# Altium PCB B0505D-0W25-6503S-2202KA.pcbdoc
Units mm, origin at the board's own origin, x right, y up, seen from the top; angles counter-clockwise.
Board outline 28 x 11 mm, 2 copper layers (Top Layer, Bottom Layer), stack 0.78 mm thick; 11 components, 8 nets, 30 pads, 14 vias.
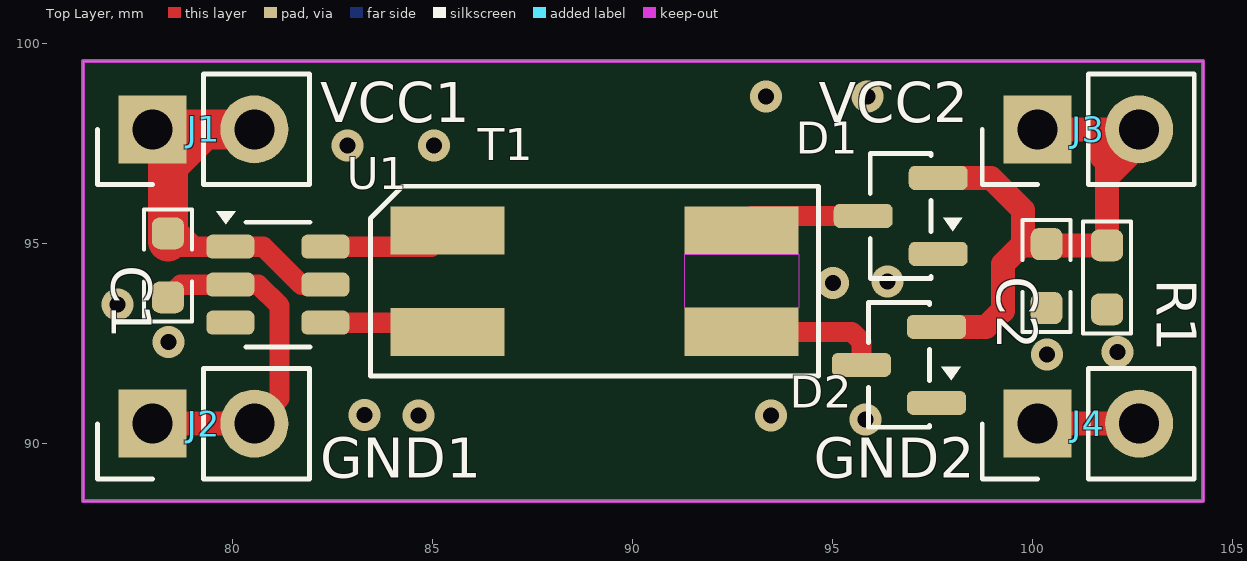
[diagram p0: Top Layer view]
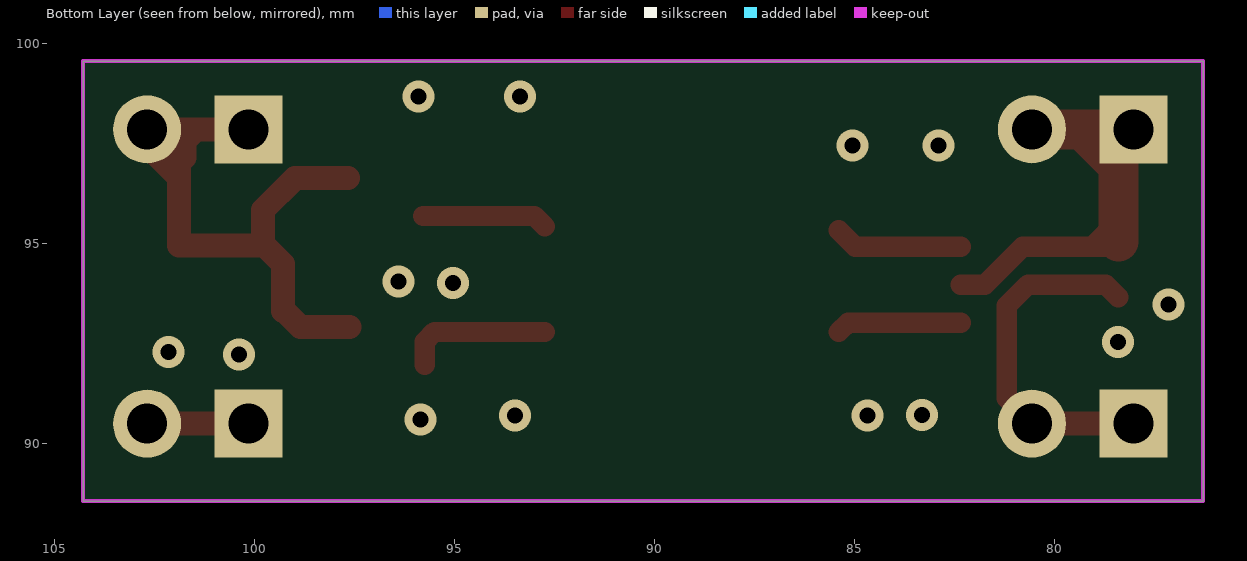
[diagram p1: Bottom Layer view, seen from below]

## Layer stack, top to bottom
Top Solder Mask Layer: solder mask 0.01, Dk 0
Top Layer: signal copper 0.035
dielectric 1: surface 0.71, FR4, Dk 4.5
Bottom Layer: signal copper 0.035
Bottom Solder Mask Layer: solder mask 0.01, Dk 0

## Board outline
76.273,99.565 104.273,99.565 104.273,88.565 76.273,88.565

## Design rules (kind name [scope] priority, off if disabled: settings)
BoardOutlineClearance copperThickness1oz [All] p0: genericclearance=0.254 ignorepadtopadclearanceinfootprint=FALSE except(0: Arc-SplitContinuation Track-SplitContinuation SMDPad-SplitContinuation THPad-SplitContinuation Via-SplitContinuation Fill-SplitContinuation Poly-SplitContinuation Region-SplitContinuation Text-SplitContinuation)
BoardOutlineClearance otherClearance [All] p0: genericclearance=0.254 ignorepadtopadclearanceinfootprint=FALSE except(0: Arc-SplitContinuation Track-SplitContinuation SMDPad-SplitContinuation THPad-SplitContinuation Via-SplitContinuation Fill-SplitContinuation Poly-SplitContinuation Region-SplitContinuation Text-SplitContinuation)
Clearance copperThickness1oz [All] p1: gap=0.178 ignorepadtopadclearanceinfootprint=FALSE
Clearance otherClearance [All] p1: gap=0.178 ignorepadtopadclearanceinfootprint=FALSE
DiffPairsRouting differentialPair [All] p1: maxuncoupledlength=10 minlimit=5 maxlimit=Infinity mostfreqgap=6 toplayer_minwidth=5 toplayer_prefwidth=100 toplayer_maxwidth=100 bottomlayer_minwidth=5 bottomlayer_prefwidth=100 bottomlayer_maxwidth=100
PasteMaskExpansion pasteMaskExpansion [All] p1: expansion=0
PlaneConnect innerPlane [All] p1: planeconnectstyle=Relief reliefexpansion=0.508 reliefentries=4 reliefconductorwidth=0.254 reliefairgap=0.254
PolygonConnect copper0 [All] p1: connectstyle=Direct reliefentries=4 reliefconductorwidth=10 polygonreliefangle="90 Angle" airgapwidth=10
RoutingVias viaSize [All] p1: viastyle="Through Hole" holewidth=24 minholewidth=11.811 maxholewidth=393.7 width=24 minwidth=11.811 maxwidth=393.7
SolderMaskExpansion solderMaskExpansion [All] p1: useseparateexpansions=TRUE expansion=2 expansionbottom=2
Width copperThickness1oz [All] p1: maxlimit=100 minlimit=5 preferedwidth=10

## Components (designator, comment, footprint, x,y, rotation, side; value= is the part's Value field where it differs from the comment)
C1 "1uF" C0603 78.393,94.461 r90 top
C2 "4.7uF" C0603 100.363,94.191 r90 top
D1 "BAT54S,215" SOT-23-3_L3.0-W1.7-P0.95-LS2.9-BR 96.713,95.694 r180 top
D2 "BAT54S,215" SOT-23-3_L3.0-W1.7-P0.95-LS2.9-BR 96.671,91.971 r180 top
J1 "KH-2.54PH180-1X2P-L11.5" HDR-TH_2P-P2.54-V-M 78.013,97.861 r90 top
J2 "KH-2.54PH180-1X2P-L11.5" HDR-TH_2P-P2.54-V-M 78.013,90.501 r90 top
J3 "KH-2.54PH180-1X2P-L11.5" HDR-TH_2P-P2.54-V-M 100.133,97.861 r90 top
J4 "KH-2.54PH180-1X2P-L11.5" HDR-TH_2P-P2.54-V-M 100.133,90.501 r90 top
R1 "4.7kΩ" R0603 101.873,94.161 r270 top
T1 "CMT2202KA" XFMR-SMD_CMT220KA 89.058,94.065 r0 top
U1 "CMP6503S" SOT-23-5_L2.9-W1.6-P0.95-LS2.8-BR 81.143,93.978 r0 top

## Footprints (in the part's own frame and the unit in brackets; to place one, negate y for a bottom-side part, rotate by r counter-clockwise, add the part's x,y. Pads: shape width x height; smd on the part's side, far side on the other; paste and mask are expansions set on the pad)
C0603 [mm]
  rrect50% 0.8x0.8 smd: 1(-0.8,0) 2(0.8,0)
  silkscreen extent -1.4,-0.6 1.4,0.6
HDR-TH_2P-P2.54-V-M [mm]
  rect 1.7x1.7 hole 1: 1(0,0)
  round 1.7 hole 1: 2(0,-2.54)
  silkscreen extent -1.38,-3.92 1.38,1.38
R0603 [mm]
  rrect50% 0.8x0.8 smd: 1(-0.8,0) 2(0.8,0)
  silkscreen extent -1.4,-0.6 1.4,0.6
SOT-23-3_L3.0-W1.7-P0.95-LS2.9-BR [mm]
  rrect50% 1.475x0.6 smd: 1(-0.937,0.95) 2(-0.937,-0.95) 3(0.938,0)
  silkscreen extent -1.54,-1.56 0.76,1.56
SOT-23-5_L2.9-W1.6-P0.95-LS2.8-BR [mm]
  rrect50% 1.2x0.6 smd: 1(-1.188,0.95) 2(-1.188,0) 3(-1.188,-0.95) 4(1.188,-0.95) 5(1.188,0) 6(1.188,0.95)
  silkscreen extent -1.54,-1.56 0.8,1.84
XFMR-SMD_CMT220KA [mm]
  rect 2.85x1.2 smd: 1(-3.675,1.27) 2(-3.675,-1.27) 3(3.675,-1.27) 4(3.675,1.27)
  silkscreen extent -5.6,-2.37 5.6,2.37

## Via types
v1: diameter 0.8, hole 0.4, Top Layer to Bottom Layer, 14 vias

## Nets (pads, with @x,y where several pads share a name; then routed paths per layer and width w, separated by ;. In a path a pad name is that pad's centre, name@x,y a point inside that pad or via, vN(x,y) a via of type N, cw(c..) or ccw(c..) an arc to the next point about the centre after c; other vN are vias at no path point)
$1N5: T1.2 U1.4 | length 3.1
  Top Layer w0.508: U1.4 85.151,93.027 T1.2
$1N6: T1.1 U1.6 | length 3.2
  Top Layer w0.508: U1.6 84.975,94.928 T1.1
$1N7: D1.3 T1.4 | length 3.2
  Top Layer w0.508: T1.4@92.733,95.431 92.996,95.694 D1.3
$1N8: D2.3 T1.3 | length 3.7
  Top Layer w0.508: T1.3 95.489,92.795 95.733,92.551 D2.3
GND1: C1.1 J2.1 J2.2 U1.2 | length 8.9
  Top Layer w0.508: C1.1 78.709,93.978 U1.2 80.651,93.978 81.183,93.446 81.183,91.131 J2.2
  Top Layer w0.6: J2.1 J2.2
  other v1: 84.663,90.701 83.303,90.721 78.403,92.541 77.133,93.481 82.884,97.451 85.043,97.451
GND2: C2.1 D1.1 D2.1 J4.1 J4.2 R1.2 | length 2.5
  Top Layer w0.6: J4.1 J4.2
  other v1: 95.833,90.601 93.472,90.701 100.373,92.231 102.133,92.291 95.023,94.021 96.383,94.061 93.345,98.676 95.885,98.676
VCC1: C1.2 J1.1 J1.2 U1.1 U1.5 | length 12.2
  Top Layer w0.508: J1.1 J1.1@78.393,97.481 ; C1.2@78.393,95.051 C1.2@78.421,95.024 ; C1.2 78.726,94.928 79.046,94.928 ; C1.2@78.393,95.581 79.046,94.928 ; U1.5 81.731,93.978 80.781,94.928 U1.1 79.046,94.928
  Top Layer w1: J1.1 79.303,97.861 ; C1.2@78.393,95.051 C1.2 78.393,95.581 78.393,96.951 ; J1.1@78.393,97.481 78.393,96.951 ; J1.2 79.303,97.861 ; 78.393,96.951 79.303,97.861
VCC2: C2.2 D1.2 D2.2 J3.1 J3.2 R1.1 | length 17.2
  Top Layer w0.6: D2.2 98.843,92.921 99.243,93.321 99.273,93.321 99.273,94.491 99.773,94.991 ; D1.2 98.97,96.644 99.773,95.841 99.773,94.991 ; J3.1 101.453,97.861 ; 99.773,94.991 99.803,94.961 R1.1 101.873,96.651 ; 101.453,97.861 101.745,97.569 ; 101.453,97.861 101.745,97.861 ; 101.745,97.569 101.745,97.159 101.873,97.031 ; 101.745,97.569 101.745,97.861 ; 101.745,97.569 101.873,97.441 101.873,97.031 ; 101.745,97.861 J3.2 102.673,97.451 101.873,96.651 ; 101.873,96.651 101.873,97.031
pads on no net: U1.3

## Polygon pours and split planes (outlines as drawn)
GND1 on Top Layer (solid, remove dead copper, pour order 2): 86.805,88.77 76.2,88.77 76.2,99.311 86.805,99.311
GND1 on Bottom Layer (solid, remove dead copper, pour order 8): 86.805,88.77 76.454,88.77 76.454,99.311 86.805,99.311
GND2 on Top Layer (solid, remove dead copper, pour order 6): 104.521,88.77 91.303,88.77 91.303,99.311 104.521,99.311
GND2 on Bottom Layer (solid, remove dead copper, pour order 12): 104.394,88.77 91.303,88.77 91.303,99.311 104.394,99.311

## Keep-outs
Top Layer:
  region: 91.308,94.735 94.158,94.735 94.158,93.395 91.308,93.395
Board Outline Layer:
  the board outline again, w0.1

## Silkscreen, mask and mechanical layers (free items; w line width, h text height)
Top Silkscreen Layer:
  text "VCC1" at 82.203,98.041 h1
  text "VCC2" at 94.658,98.041 h1
  text "GND1" at 82.203,89.155 h1
  text "GND2" at 94.533,89.155 h1
User.Eco1:
